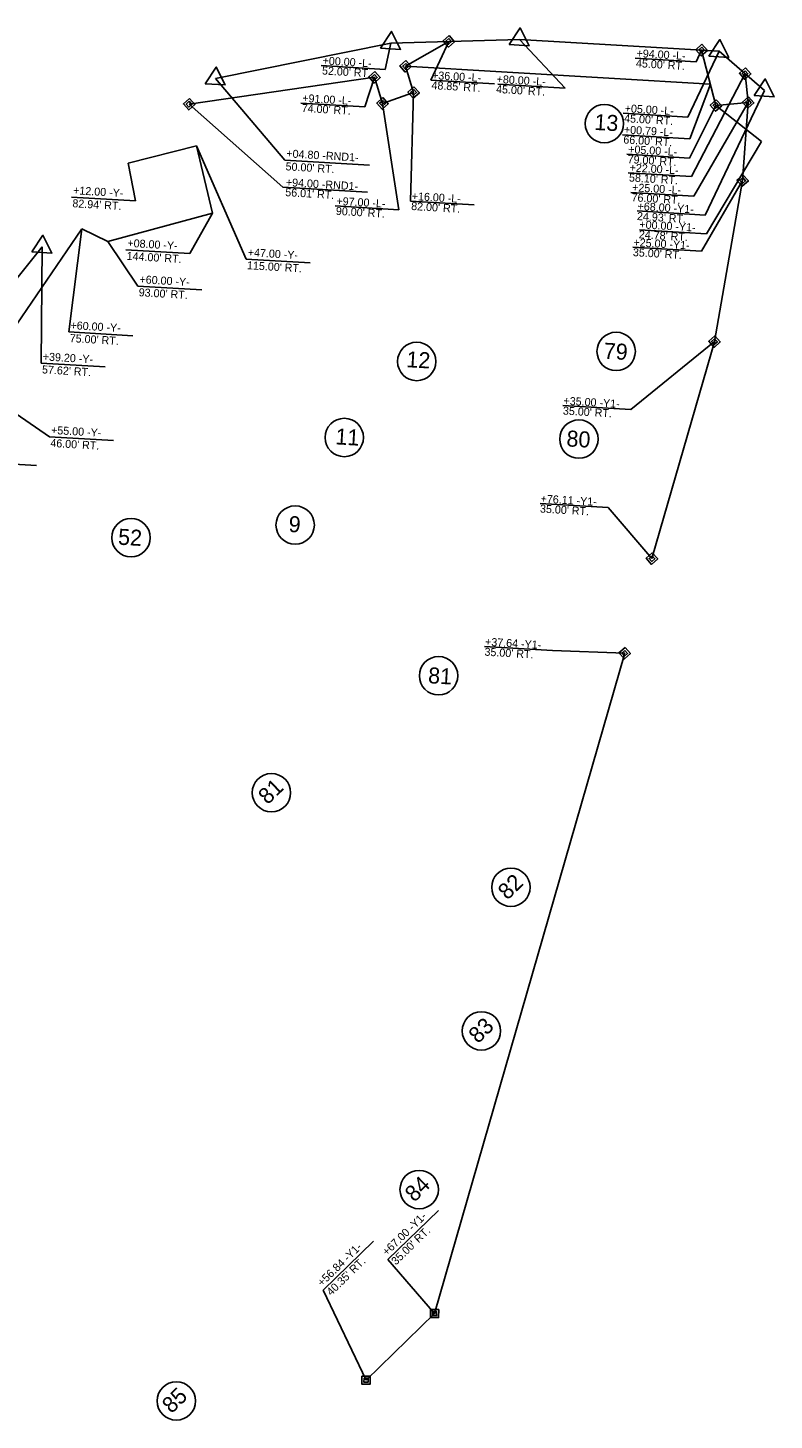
# Model space of a CAD drawing. Extents: x 2010883 to 2014849, y 442000 to 447413.
# Drawn here: x 2011908 to 2012374, y 444067 to 444937 of the extents above; entities that cross this region are included whole.
import ezdxf

# ---------------------------------------------------------------- set-up
doc = ezdxf.new("R2010")
doc.units = 0
for name, color, linetype in [('Prop Easement Construction', 7, 'Continuous'), ('Prop Easement Construction Station Offsets', 7, 'Continuous'), ('Prop Easement Permanent Drainage', 7, 'Continuous'), ('Prop Easement Permanent Drainage Station Offsets', 7, 'Continuous'), ('Prop Easement Permanent Utility', 7, 'Continuous'), ('Prop Easement Permanent Utility Station Offsets', 7, 'Continuous'), ('Prop Parcel Number CELL', 7, 'Continuous'), ('Prop Parcel Number Text', 7, 'Continuous'), ('Prop ROW Marker CELL', 7, 'Continuous'), ('Prop ROW Permanent Easement CELL', 7, 'Continuous'), ('Prop ROW RW Lines', 7, 'Continuous'), ('Prop ROW Station Offsets', 7, 'Continuous')]:
    doc.layers.add(name, color=color, linetype=linetype)

msp = doc.modelspace()

# ---------------------------------------------------------------- linework, layer by layer
at = {"layer": 'Prop Easement Construction'}
for p, q in [((2012143.95, 444913.2), (2012334.41, 444901.97)), ((2012337.85, 444888.75), (2012366.3, 444866.14)), ((2011970.7, 444852.57), (2012013.35, 444863.48)), ((2012023.37, 444821.5), (2012013.35, 444863.48)), ((2011957.93, 444803.73), (2012023.37, 444821.5)), ((2011864.2, 444698.09), (2011941.73, 444811.57)), ((2011941.73, 444811.57), (2011957.93, 444803.73))]:
    msp.add_line(p, q, dxfattribs=at)
at = {"layer": 'Prop Easement Construction Station Offsets'}
for p, q in [((2012334.41, 444901.97), (2012321.63, 444867.97)), ((2012013.35, 444863.48), (2012044.44, 444792.75)), ((2012279.46, 444870.46), (2012321.63, 444867.97)), ((2012366.3, 444866.14), (2012331.94, 444808.58)), ((2011970.7, 444852.57), (2011975.3, 444829.14)), ((2011935.37, 444831.5), (2011975.3, 444829.14)), ((2012023.37, 444821.5), (2012009.18, 444796.25)), ((2011941.73, 444811.57), (2011933.7, 444747.22)), ((2012290.02, 444811.05), (2012331.94, 444808.58)), ((2011957.93, 444803.73), (2011976.8, 444775.89)), ((2011969.25, 444798.6), (2012009.18, 444796.25)), ((2012044.44, 444792.75), (2012084.37, 444790.4)), ((2011976.8, 444775.89), (2012016.73, 444773.54)), ((2011933.7, 444747.22), (2011973.63, 444744.87)), ((2011873.43, 444666.16), (2011913.36, 444663.81))]:
    msp.add_line(p, q, dxfattribs=at)
at = {"layer": 'Prop Easement Permanent Drainage'}
for p, q in [((2012354.52, 444841.83), (2012357.99, 444890.56)), ((2012336.92, 444741.17), (2012354.52, 444841.83)), ((2012297.88, 444605.56), (2012337.3, 444742.48)), ((2012162.08, 444133.83), (2012280.86, 444546.44)), ((2012119.25, 444092.18), (2012162.08, 444133.83))]:
    msp.add_line(p, q, dxfattribs=at)
at = {"layer": 'Prop Easement Permanent Drainage Station Offsets'}
for p, q in [((2012354.52, 444841.83), (2012328.74, 444797.71)), ((2012285.99, 444800.23), (2012328.74, 444797.71)), ((2012284.71, 444698.72), (2012336.92, 444741.17)), ((2012242.29, 444701.22), (2012284.71, 444698.72)), ((2012227.99, 444640.01), (2012270.41, 444637.51)), ((2012270.41, 444637.51), (2012297.88, 444605.56)), ((2012193.29, 444550.59), (2012235.71, 444548.09)), ((2012193.29, 444550.59), (2012235.71, 444548.09)), ((2012235.71, 444548.09), (2012280.86, 444546.44)), ((2012132.88, 444167.64), (2012164.43, 444198.31)), ((2012092.42, 444148.48), (2012123.97, 444179.15)), ((2012162.08, 444133.83), (2012132.88, 444167.64)), ((2012119.25, 444092.18), (2012092.42, 444148.48))]:
    msp.add_line(p, q, dxfattribs=at)
at = {"layer": 'Prop Easement Permanent Utility'}
for p, q in [((2012143.95, 444913.2), (2012170.91, 444928.79)), ((2012328.87, 444923.33), (2012337.85, 444888.75)), ((2012149, 444896.87), (2012143.95, 444913.2)), ((2012357.99, 444890.56), (2012356.05, 444908.61)), ((2012008.74, 444889.51), (2012124.51, 444906.33)), ((2012124.51, 444906.33), (2012129.56, 444890)), ((2012129.56, 444890), (2012149, 444896.87)), ((2012337.85, 444888.75), (2012357.99, 444890.56))]:
    msp.add_line(p, q, dxfattribs=at)
at = {"layer": 'Prop Easement Permanent Utility Station Offsets'}
for p, q in [((2012170.91, 444928.79), (2012159.64, 444904.53)), ((2012287.36, 444918.18), (2012325.49, 444915.93)), ((2012328.87, 444923.33), (2012325.49, 444915.93)), ((2012356.05, 444908.61), (2012322.52, 444844.39)), ((2012124.51, 444906.33), (2012118.5, 444887.88)), ((2012159.64, 444904.53), (2012199.57, 444902.18)), ((2012008.74, 444889.51), (2012067.34, 444837.63)), ((2012078.56, 444890.23), (2012118.5, 444887.88)), ((2012129.56, 444890), (2012139.83, 444823.59)), ((2012149, 444896.87), (2012146.94, 444828.98)), ((2012357.99, 444890.56), (2012323.99, 444832.03)), ((2012337.85, 444888.75), (2012321.31, 444855.88)), ((2012282.14, 444858.19), (2012321.31, 444855.88)), ((2012283, 444846.72), (2012322.52, 444844.39)), ((2012067.34, 444837.63), (2012120.25, 444834.51)), ((2012146.94, 444828.98), (2012186.87, 444826.62)), ((2012284.61, 444834.35), (2012323.99, 444832.03)), ((2012099.9, 444825.94), (2012139.83, 444823.59))]:
    msp.add_line(p, q, dxfattribs=at)
at = {"layer": 'Prop Parcel Number CELL'}
for p, q in [((2012268.15, 444877.39), (2012268.15, 444877.39)), ((2012275.51, 444735.03), (2012275.51, 444735.03)), ((2012150.93, 444728.75), (2012150.93, 444728.75)), ((2012105.66, 444681.25), (2012105.66, 444681.25)), ((2012252.22, 444680.24), (2012252.22, 444680.24)), ((2012075, 444626.53), (2012075, 444626.53)), ((2011972.45, 444618.64), (2011972.45, 444618.64)), ((2012164.57, 444532.37), (2012164.57, 444532.37)), ((2012060.16, 444459.28), (2012060.16, 444459.28)), ((2012209.74, 444400.17), (2012209.74, 444400.17)), ((2012191.36, 444310.45), (2012191.36, 444310.45)), ((2012152.46, 444211.3), (2012152.46, 444211.3)), ((2012000.75, 444079.2), (2012000.75, 444079.2))]:
    msp.add_line(p, q, dxfattribs=at)
for centre in [(2012268.15, 444877.39), (2012275.51, 444735.03), (2012150.93, 444728.75), (2012105.66, 444681.25), (2012252.22, 444680.24), (2012075, 444626.53), (2011972.45, 444618.64), (2012164.57, 444532.37), (2012060.16, 444459.28), (2012209.74, 444400.17), (2012191.36, 444310.45), (2012152.46, 444211.3), (2012000.75, 444079.2)]:
    msp.add_circle(centre, 12, dxfattribs=at)
at = {"layer": 'Prop ROW Marker CELL'}
for p, q in [((2012134.79, 444927.76), (2012134.79, 444927.76)), ((2012170.91, 444928.79), (2012170.91, 444928.79)), ((2012215.07, 444930.04), (2012215.07, 444930.04)), ((2012328.87, 444923.33), (2012328.87, 444923.33)), ((2012339.85, 444922.69), (2012339.85, 444922.69)), ((2012143.95, 444913.2), (2012143.95, 444913.2)), ((2012356.05, 444908.61), (2012356.05, 444908.61)), ((2012025.24, 444905.54), (2012025.24, 444905.54)), ((2012124.51, 444906.33), (2012124.51, 444906.33)), ((2012368.17, 444898.09), (2012368.17, 444898.09)), ((2012008.74, 444889.51), (2012008.74, 444889.51)), ((2012129.56, 444890), (2012129.56, 444890)), ((2012149, 444896.87), (2012149, 444896.87)), ((2012357.99, 444890.56), (2012357.99, 444890.56)), ((2012337.85, 444888.75), (2012337.85, 444888.75)), ((2012354.52, 444841.83), (2012354.52, 444841.83)), ((2011917.02, 444800.42), (2011917.02, 444800.42)), ((2012336.92, 444741.17), (2012336.92, 444741.17)), ((2012297.88, 444605.56), (2012297.88, 444605.56)), ((2012280.86, 444546.44), (2012280.86, 444546.44)), ((2012162.08, 444133.83), (2012162.08, 444133.83)), ((2012119.25, 444092.18), (2012119.25, 444092.18))]:
    msp.add_line(p, q, dxfattribs=at)
for points in [[(2012128.34, 444924.54), (2012135.22, 444934.95), (2012140.82, 444923.8)], [(2012208.61, 444926.82), (2012215.49, 444937.23), (2012221.09, 444926.08)], [(2012333.4, 444919.46), (2012340.27, 444929.87), (2012345.88, 444918.72)], [(2012018.78, 444902.31), (2012025.66, 444912.73), (2012031.26, 444901.58)], [(2012361.71, 444894.86), (2012368.59, 444905.27), (2012374.19, 444894.12)], [(2011910.57, 444797.2), (2011917.45, 444807.61), (2011923.05, 444796.46)]]:
    msp.add_lwpolyline(points, close=True, dxfattribs=at)
at = {"layer": 'Prop ROW Permanent Easement CELL'}
for points in [[(2012171.13, 444932.38), (2012174.51, 444928.58), (2012170.7, 444925.19), (2012167.32, 444929)], [(2012171.02, 444930.58), (2012172.71, 444928.68), (2012170.81, 444926.99), (2012169.12, 444928.89)], [(2012329.08, 444926.93), (2012332.46, 444923.12), (2012328.66, 444919.74), (2012325.27, 444923.55)], [(2012328.97, 444925.13), (2012330.66, 444923.23), (2012328.76, 444921.54), (2012327.07, 444923.44)], [(2012144.16, 444916.79), (2012147.54, 444912.99), (2012143.74, 444909.6), (2012140.36, 444913.41)], [(2012124.72, 444909.92), (2012128.11, 444906.12), (2012124.3, 444902.74), (2012120.92, 444906.54)], [(2012124.62, 444908.13), (2012126.31, 444906.22), (2012124.41, 444904.53), (2012122.72, 444906.44)], [(2012144.06, 444914.99), (2012145.75, 444913.09), (2012143.84, 444911.4), (2012142.15, 444913.3)], [(2012356.26, 444912.21), (2012359.64, 444908.4), (2012355.84, 444905.02), (2012352.45, 444908.82)], [(2012356.15, 444910.41), (2012357.85, 444908.51), (2012355.94, 444906.82), (2012354.25, 444908.72)], [(2012149.21, 444900.47), (2012152.59, 444896.66), (2012148.79, 444893.28), (2012145.4, 444897.08)], [(2012149.1, 444898.67), (2012150.8, 444896.77), (2012148.89, 444895.08), (2012147.2, 444896.98)], [(2012008.95, 444893.11), (2012012.33, 444889.3), (2012008.53, 444885.92), (2012005.15, 444889.73)], [(2012008.85, 444891.31), (2012010.54, 444889.41), (2012008.63, 444887.72), (2012006.94, 444889.62)], [(2012129.77, 444893.6), (2012133.15, 444889.79), (2012129.35, 444886.41), (2012125.97, 444890.22)], [(2012129.67, 444891.8), (2012131.36, 444889.9), (2012129.45, 444888.21), (2012127.76, 444890.11)], [(2012338.06, 444892.34), (2012341.44, 444888.53), (2012337.64, 444885.15), (2012334.25, 444888.96)], [(2012337.95, 444890.54), (2012339.64, 444888.64), (2012337.74, 444886.95), (2012336.05, 444888.85)], [(2012358.2, 444894.16), (2012361.58, 444890.35), (2012357.78, 444886.97), (2012354.4, 444890.77)], [(2012358.1, 444892.36), (2012359.79, 444890.46), (2012357.88, 444888.77), (2012356.19, 444890.67)], [(2012354.73, 444845.43), (2012358.11, 444841.62), (2012354.31, 444838.24), (2012350.93, 444842.05)], [(2012354.63, 444843.63), (2012356.32, 444841.73), (2012354.41, 444840.04), (2012352.72, 444841.94)], [(2012337.13, 444744.76), (2012340.51, 444740.96), (2012336.71, 444737.57), (2012333.32, 444741.38)], [(2012337.02, 444742.96), (2012338.72, 444741.06), (2012336.81, 444739.37), (2012335.12, 444741.27)], [(2012298.09, 444609.16), (2012301.48, 444605.35), (2012297.67, 444601.97), (2012294.29, 444605.78)], [(2012297.99, 444607.36), (2012299.68, 444605.46), (2012297.78, 444603.77), (2012296.09, 444605.67)], [(2012281.07, 444550.03), (2012284.46, 444546.23), (2012280.65, 444542.85), (2012277.27, 444546.65)], [(2012280.97, 444548.24), (2012282.66, 444546.33), (2012280.76, 444544.64), (2012279.06, 444546.55)], [(2012159.57, 444136.41), (2012164.66, 444136.34), (2012164.59, 444131.25), (2012159.5, 444131.32)], [(2012160.83, 444135.12), (2012163.37, 444135.09), (2012163.34, 444132.54), (2012160.79, 444132.58)], [(2012116.74, 444094.76), (2012121.83, 444094.69), (2012121.76, 444089.6), (2012116.67, 444089.67)], [(2012117.99, 444093.47), (2012120.54, 444093.43), (2012120.5, 444090.89), (2012117.96, 444090.92)]]:
    msp.add_lwpolyline(points, close=True, dxfattribs=at)
at = {"layer": 'Prop ROW RW Lines'}
for p, q in [((2012025.24, 444905.54), (2012134.79, 444927.76)), ((2012134.79, 444927.76), (2012215.07, 444930.04)), ((2012215.07, 444930.04), (2012339.85, 444922.69)), ((2012339.85, 444922.69), (2012368.17, 444898.09)), ((2011857.11, 444725.89), (2011917.02, 444800.42))]:
    msp.add_line(p, q, dxfattribs=at)
at = {"layer": 'Prop ROW Station Offsets'}
for p, q in [((2012131.17, 444911.27), (2012134.79, 444927.76)), ((2012243.58, 444899.52), (2012215.07, 444930.04)), ((2012320.33, 444881.46), (2012339.85, 444922.69)), ((2012091.24, 444913.63), (2012131.17, 444911.27)), ((2012068.54, 444854.56), (2012025.24, 444905.54)), ((2012201.55, 444902), (2012243.58, 444899.52)), ((2012331.01, 444820.28), (2012368.17, 444898.09)), ((2012279.96, 444883.84), (2012320.33, 444881.46)), ((2012068.54, 444854.56), (2012121.45, 444851.44)), ((2012288.56, 444822.79), (2012331.01, 444820.28)), ((2011916.4, 444727.67), (2011917.02, 444800.42)), ((2011921.57, 444681.71), (2011857.11, 444725.89)), ((2011916.4, 444727.67), (2011956.33, 444725.31)), ((2011921.57, 444681.71), (2011961.5, 444679.36))]:
    msp.add_line(p, q, dxfattribs=at)

# ---------------------------------------------------------------- texts
at = {"layer": 'Prop Easement Construction Station Offsets'}
for s, p in [('+00.79 -L-', (2012280.23, 444871.24)), ("66.00' RT.", (2012279.86, 444865)), ('+12.00 -Y-', (2011936.2, 444833.28)), ("82.94' RT.", (2011935.72, 444825.17)), ('+00.00 -Y1-', (2012289.9, 444811.99)), ('+08.00 -Y-', (2011970.08, 444800.39)), ("24.78' RT.", (2012289.54, 444805.75)), ("144.00' RT.", (2011969.6, 444792.28)), ('+47.00 -Y-', (2012045.27, 444794.54)), ("115.00' RT.", (2012044.79, 444786.42)), ('+60.00 -Y-', (2011977.63, 444777.68)), ("93.00' RT.", (2011977.15, 444769.56)), ('+60.00 -Y-', (2011934.53, 444749.01)), ("75.00' RT.", (2011934.05, 444740.9))]:
    msp.add_text(s, height=5, rotation=356.62643, dxfattribs=at).set_placement(p)
at = {"layer": 'Prop Easement Permanent Drainage Station Offsets'}
for s, rotation, p in [('+25.00 -Y1-', 356.62643, (2012286.2, 444800.84)), ("35.00' RT.", 356.62643, (2012285.83, 444794.6)), ('+35.00 -Y1-', 356.62643, (2012242.5, 444701.82)), ("35.00' RT.", 356.62643, (2012242.13, 444695.59)), ("35.00' RT.", 356.62643, (2012227.83, 444634.37)), ('+76.11 -Y1-', 356.62643, (2012228.2, 444640.61)), ("35.00' RT.", 356.62643, (2012193.13, 444544.95)), ('+37.64 -Y1-', 356.62643, (2012193.5, 444551.19)), ('+67.00 -Y1-', 44.19825, (2012132.28, 444169.61)), ("35.00' RT.", 44.19825, (2012137.95, 444163.78)), ('+56.84 -Y1-', 44.19825, (2012091.82, 444150.45)), ("40.35' RT.", 44.19825, (2012097.49, 444144.62))]:
    msp.add_text(s, height=5, rotation=rotation, dxfattribs=at).set_placement(p)
at = {"layer": 'Prop Easement Permanent Utility Station Offsets'}
for s, p in [("45.00' RT.", (2012287.76, 444912.73)), ('+94.00 -L-', (2012288.13, 444918.97)), ('+36.00 -L-', (2012160.4, 444905.24)), ("48.85' RT.", (2012160.03, 444899)), ("74.00' RT.", (2012078.96, 444884.7)), ('+91.00 -L-', (2012079.33, 444890.94)), ('+05.00 -L-', (2012282.91, 444858.98)), ("79.00' RT.", (2012282.54, 444852.74)), ("58.10' RT.", (2012283.41, 444841.27)), ('+22.00 -L-', (2012283.78, 444847.51)), ("56.01' RT.", (2012068.7, 444832.1)), ('+94.00 -RND1-', (2012069.07, 444838.34)), ('+25.00 -L-', (2012285.38, 444835.14)), ('+97.00 -L-', (2012100.66, 444826.65)), ("82.00' RT.", (2012147.34, 444823.44)), ('+16.00 -L-', (2012147.71, 444829.68)), ("76.00' RT.", (2012285.01, 444828.9)), ("90.00' RT.", (2012100.3, 444820.41))]:
    msp.add_text(s, height=5, rotation=356.62643, dxfattribs=at).set_placement(p)
at = {"layer": 'Prop Parcel Number Text'}
for s, rotation, p in [('13', 356.62643, (2012261.73, 444873.47)), ('12', 356.62643, (2012144.28, 444725.22)), ('79', 356.62643, (2012267.56, 444730.53)), ('11', 356.62643, (2012099.94, 444676.99)), ('80', 356.62643, (2012244.27, 444675.74)), ('9', 356.62643, (2012070.69, 444622.27)), ('52', 356.62643, (2011964.17, 444614.31)), ('81', 356.62643, (2012157.84, 444527.74)), ('81', 44.19825, (2012057.83, 444451.43)), ('82', 44.19825, (2012207.58, 444391.84)), ('83', 44.19825, (2012189.21, 444302.11)), ('84', 44.19825, (2012149.46, 444203.01)), ('85', 44.19825, (2011997.76, 444070.91))]:
    msp.add_text(s, height=10, rotation=rotation, dxfattribs=at).set_placement(p)
at = {"layer": 'Prop ROW Station Offsets'}
for s, p in [('+00.00 -L-', (2012092.01, 444914.37)), ("52.00' RT.", (2012091.65, 444908.13)), ('+80.00 -L-', (2012200.74, 444902.81)), ("45.00' RT.", (2012200.38, 444896.57)), ('+05.00 -L-', (2012280.73, 444884.55)), ("45.00' RT.", (2012280.36, 444878.31)), ('+04.80 -RND1-', (2012069.37, 444856.34)), ("50.00' RT.", (2012068.9, 444848.23)), ("24.93' RT.", (2012288.4, 444817.15)), ('+68.00 -Y1-', (2012288.77, 444823.39)), ('+39.20 -Y-', (2011917.23, 444729.45)), ("57.62' RT.", (2011916.75, 444721.34)), ('+55.00 -Y-', (2011922.41, 444683.5)), ("46.00' RT.", (2011921.93, 444675.39))]:
    msp.add_text(s, height=5, rotation=356.62643, dxfattribs=at).set_placement(p)

doc.saveas('drawing.dxf')
